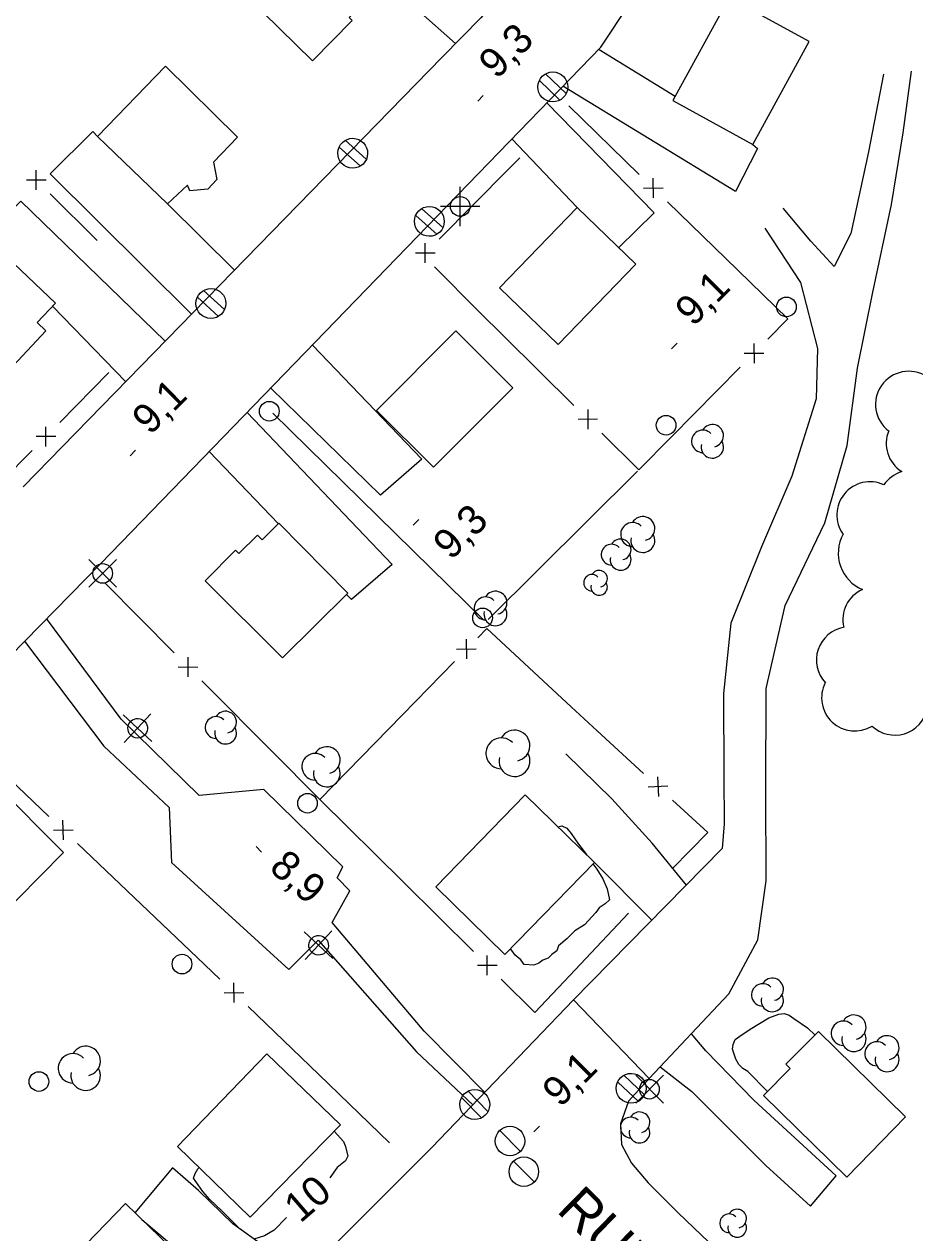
# Model space of a CAD drawing. Extents: x 381879 to 384696, y 5564785 to 5567594.
# Drawn here: x 383271.9 to 383362.5, y 5565478.7 to 5565601.7 of the extents above; entities that cross this region are included whole.
import ezdxf

# ---------------------------------------------------------------- set-up
doc = ezdxf.new("R2010")
doc.units = 0
for name, color, linetype in [('Niveau 1', 7, 'Continuous'), ('Niveau 19', 7, 'Continuous'), ('Niveau 21', 7, 'Continuous'), ('Niveau 22', 7, 'Continuous'), ('Niveau 3', 7, 'Continuous'), ('Niveau 31', 7, 'Continuous'), ('Niveau 36', 7, 'Continuous'), ('Niveau 37', 7, 'Continuous'), ('Niveau 41', 7, 'Continuous'), ('Niveau 44', 7, 'Continuous')]:
    doc.layers.add(name, color=color, linetype=linetype)

msp = doc.modelspace()

# ---------------------------------------------------------------- linework, layer by layer
at = {"layer": 'Niveau 1'}
for points in [[(383326.21, 5565520.01), (383326.61, 5565520.1), (383327.12, 5565519.86), (383327.57, 5565519.34), (383328.31, 5565518.24), (383329.12, 5565517.18), (383329.12, 5565517.17)], [(383329.78, 5565516.24), (383330.17, 5565515.69), (383330.78, 5565514.72), (383331.24, 5565513.69), (383331.47, 5565512.59), (383331.03, 5565512.17), (383330.41, 5565511.77), (383330.06, 5565511.31), (383328.91, 5565510.04), (383327.94, 5565509.43), (383327.13, 5565508.62)], [(383327.13, 5565508.62), (383326.29, 5565507.89), (383326.12, 5565507.4), (383325.58, 5565507.03), (383325.21, 5565506.64), (383324.68, 5565506.45), (383324.28, 5565506.14), (383323.76, 5565505.95), (383322.79, 5565506.02), (383322.45, 5565506.49), (383321.86, 5565506.96), (383321.52, 5565507.43), (383321.38, 5565507.6)], [(383347.56, 5565493.1), (383345.53, 5565495.12), (383345.02, 5565495.44), (383344.64, 5565495.83), (383344.34, 5565496.36), (383344, 5565497.38), (383344.05, 5565497.88), (383344.25, 5565498.36), (383344.72, 5565498.72), (383345.79, 5565499.42), (383347.68, 5565500.57), (383348.7, 5565500.96), (383349.23, 5565501.01), (383349.74, 5565500.86), (383350.21, 5565500.52), (383351.63, 5565499.57), (383352.39, 5565498.83)], [(383303.45, 5565489.04), (383304.41, 5565487.98), (383304.61, 5565487.48), (383304.85, 5565486.5), (383304.6, 5565486.04), (383303.76, 5565485.36)], [(383293.91, 5565479.04), (383292.02, 5565480.95), (383290.8, 5565482.09), (383290.07, 5565482.91), (383289.14, 5565484.25), (383289.28, 5565484.74), (383289.58, 5565485.22), (383289.7, 5565485.36)], [(383303.76, 5565485.36), (383303, 5565484.3)], [(383298.58, 5565480.26), (383297.33, 5565478.98), (383296.35, 5565478.4), (383295.27, 5565478.06)]]:
    msp.add_lwpolyline(points, dxfattribs=at)
at = {"layer": 'Niveau 19'}
for points in [[(383308.64, 5565606.08), (383311.95, 5565603.09), (383315.79, 5565599.7)], [(383330.36, 5565599.11), (383330.41, 5565599.08), (383338.14, 5565594.34)], [(383343.62, 5565503.02), (383346.56, 5565508.52), (383347.41, 5565514.53), (383347.36, 5565523.69), (383347.41, 5565534.07), (383349.35, 5565542.53), (383353.38, 5565550.95), (383355.65, 5565558.8), (383356.72, 5565566.68), (383358.24, 5565574.24), (383360.17, 5565583.33), (383361.36, 5565590.63), (383362.21, 5565596.9)], [(383359.35, 5565596.58), (383357.84, 5565588.69), (383356.03, 5565580.39), (383354.32, 5565577.02), (383351.97, 5565579.6), (383349.15, 5565582.97)], [(383346.04, 5565589.44), (383346.54, 5565589.02), (383344.29, 5565584.65), (383326.72, 5565595.35)], [(383332.4, 5565578.95), (383336.02, 5565582.47), (383325.08, 5565593.66)], [(383279.36, 5565590.24), (383278.87, 5565590.74), (383274.54, 5565586.43), (383288.94, 5565572.18)], [(383321.54, 5565590), (383321.54, 5565590), (383328.17, 5565583.03)], [(383286.24, 5565569.41), (383271.55, 5565583.65), (383267.95, 5565580.02)], [(383293.3, 5565576.64), (383286.47, 5565583.38)], [(383347.27, 5565580.93), (383350.89, 5565575.39), (383352.64, 5565568.69), (383352.51, 5565563.55), (383350.03, 5565555.69), (383346.92, 5565548.51), (383343.81, 5565540.74), (383343.08, 5565533.56), (383343.1, 5565525.2), (383343.15, 5565520.33), (383342.94, 5565517.79)], [(383274.79, 5565572.99), (383282.23, 5565565.29)], [(383301.23, 5565569.03), (383312.37, 5565557.43), (383308.15, 5565553.75), (383297.04, 5565564.62), (383297, 5565564.66)], [(383294.59, 5565562.18), (383309.35, 5565546.69), (383305.21, 5565543.13), (383304.71, 5565543.65)], [(383297.78, 5565550.85), (383290.73, 5565558.19)], [(383339.29, 5565514.08), (383335.81, 5565518.35), (383331.72, 5565522.87), (383327.02, 5565527.45)], [(383327.73, 5565502.33), (383342.94, 5565517.79)], [(383335.77, 5565510.5), (383329.93, 5565516.39)], [(383335.5, 5565494.4), (383343.62, 5565503.02)], [(383336.62, 5565495.59), (383336.63, 5565495.59), (383339.84, 5565493.07), (383347.37, 5565485.57), (383351.93, 5565481.42), (383354.53, 5565484.5), (383346.14, 5565492.19), (383341.26, 5565497.22), (383339.8, 5565498.96), (383339.8, 5565498.96)], [(383300.39, 5565474.39), (383293.12, 5565479.61), (383289.65, 5565483.01), (383287, 5565485.32), (383283.17, 5565480.75)], [(383283.88, 5565480.06), (383291.48, 5565473.65), (383296.45, 5565470.34)]]:
    msp.add_lwpolyline(points, dxfattribs=at)
at = {"layer": 'Niveau 21'}
for points in [[(383279.7, 5565546.8), (383330.59, 5565599.35), (383333.54, 5565603.77), (383335.2, 5565607.85), (383336.77, 5565613.62), (383337.23, 5565619.22), (383336.69, 5565623.71), (383333.54, 5565649.66), (383333.88, 5565651.87), (383335.17, 5565653.84), (383337.46, 5565655.87), (383338.63, 5565656.35), (383339.61, 5565656.47)], [(383225.4, 5565600.6), (383260.79, 5565637.22), (383264.27, 5565640.61), (383268.01, 5565643.77), (383272.04, 5565645.91), (383277.7, 5565648.06), (383282.77, 5565649.18), (383314.56, 5565653.12), (383317.26, 5565652.66), (383319.46, 5565651.5), (383321.49, 5565649.13), (383322.5, 5565646.69), (383322.83, 5565644.58), (383325.81, 5565617.8), (383325.38, 5565613.29), (383324.28, 5565610.19), (383321.91, 5565606.43), (383318.36, 5565602.32), (383314.44, 5565598.32), (383271.8, 5565554.6)], [(383279.7, 5565546.8), (383267.3, 5565534.2), (383254, 5565520.6)], [(383300.6, 5565474.6), (383313.4, 5565487.4), (383327.8, 5565502.4)], [(383327.8, 5565502.4), (383335.5, 5565494.4)], [(383335.5, 5565494.4), (383333.4, 5565492.1), (383332.6, 5565489.8), (383332.7, 5565487.7), (383333.7, 5565485.8), (383335.4, 5565483.8), (383338.5, 5565480.7), (383345.4, 5565474.1), (383355.1, 5565464.2), (383360.4, 5565459)]]:
    msp.add_lwpolyline(points, dxfattribs=at)
at = {"layer": 'Niveau 22'}
for points in [[(383318.77, 5565492.99), (383312.61, 5565499.23), (383303.23, 5565510.27), (383305.05, 5565513.51), (383303.75, 5565514.81), (383304.31, 5565515.95), (383296.28, 5565523.81), (383289.69, 5565523.2), (383281.76, 5565530.95), (383274.18, 5565541.19)], [(383271.92, 5565538.9), (383280.01, 5565528.23), (383286.64, 5565521.98), (383286.88, 5565516.39), (383298.82, 5565505.51), (383301.8, 5565508.47), (383311.82, 5565497.12), (383317.56, 5565491.73)]]:
    msp.add_lwpolyline(points, dxfattribs=at)
at = {"layer": 'Niveau 3'}
for p, q in [((383318.05, 5565593.84), (383318.62, 5565594.41)), ((383337.77, 5565568.64), (383338.34, 5565569.21)), ((383282.67, 5565557.75), (383283.24, 5565558.32)), ((383311.48, 5565550.71), (383312.05, 5565551.28)), ((383295.51, 5565518.02), (383296.06, 5565517.45)), ((383323.77, 5565488.98), (383324.34, 5565489.55))]:
    msp.add_line(p, q, dxfattribs=at)
at = {"layer": 'Niveau 31'}
for points in [[(383294.52, 5565604.57), (383302.33, 5565612.51), (383308.75, 5565606.19), (383304.98, 5565602.36), (383305.29, 5565602.06), (383301.24, 5565597.94)], [(383346.04, 5565589.44), (383351.78, 5565599.91), (383343.64, 5565604.37), (383337.9, 5565593.9)], [(383279.36, 5565590.24), (383286.28, 5565597.4), (383293.61, 5565590.19), (383291.15, 5565587.65), (383291.5, 5565585.86), (383290.6, 5565584.89), (383288.75, 5565584.7), (383288.5, 5565585.3), (383286.47, 5565583.38)], [(383320.27, 5565574.85), (383328.17, 5565583.03), (383334.14, 5565577.27), (383326.24, 5565569.09)], [(383267.95, 5565580.02), (383261.3, 5565572.94), (383269.33, 5565565.39), (383274.11, 5565570.47), (383273.21, 5565571.32), (383275.07, 5565573.29)], [(383307.76, 5565562.38), (383315.82, 5565570.46), (383321.62, 5565564.67), (383313.56, 5565556.59)], [(383298.17, 5565537.2), (383304.84, 5565543.78), (383297.82, 5565550.89), (383296.11, 5565549.21), (383295.64, 5565549.69), (383293.74, 5565547.83), (383293.41, 5565548.16), (383290.3, 5565545.04)], [(383266.5, 5565507.9), (383259.6, 5565514.7), (383269, 5565524.3), (383275.9, 5565517.4)], [(383322.88, 5565523.25), (383313.78, 5565513.89), (383320.83, 5565507.03), (383329.93, 5565516.39)], [(383361.6, 5565490.5), (383355.61, 5565484.38), (383347.14, 5565492.67), (383349.85, 5565495.43), (383349.42, 5565495.86), (383352.74, 5565499.18)], [(383304.1, 5565489.7), (383294.9, 5565480.3), (383287.5, 5565487.5), (383296.6, 5565496.9)], [(383282.2, 5565481.7), (383289.3, 5565474.8), (383280.3, 5565465.5), (383273.2, 5565472.4)]]:
    msp.add_lwpolyline(points, close=True, dxfattribs=at)
at = {"layer": 'Niveau 36'}
for p, q in [((383327.05, 5565594.61), (383324.96, 5565596.62)), ((383324.33, 5565595.95), (383326.42, 5565593.94)), ((383303.95, 5565589.16), (383306.11, 5565587.24)), ((383306.71, 5565587.94), (383304.55, 5565589.86)), ((383316.27, 5565581.13), (383316.28, 5565585.11)), ((383314.51, 5565580.99), (383312.34, 5565582.91)), ((383318.27, 5565583.11), (383314.28, 5565583.13)), ((383311.75, 5565582.21), (383313.92, 5565580.29)), ((383292.28, 5565572.63), (383290.13, 5565574.58)), ((383289.52, 5565573.89), (383291.67, 5565571.94)), ((383281.3, 5565547.2), (383278.48, 5565544.38)), ((383281.3, 5565544.38), (383278.48, 5565547.2)), ((383281.98, 5565531.4), (383284.89, 5565528.68)), ((383282.08, 5565528.59), (383284.8, 5565531.5)), ((383300.39, 5565509.32), (383303.3, 5565506.6)), ((383300.49, 5565506.51), (383303.21, 5565509.42)), ((383335.03, 5565492.75), (383332.92, 5565494.74)), ((383336.95, 5565494.73), (383334.13, 5565491.91)), ((383336.95, 5565491.91), (383334.13, 5565494.73)), ((383319.09, 5565491.06), (383317.06, 5565493.14)), ((383332.31, 5565494.05), (383334.42, 5565492.06)), ((383316.41, 5565492.48), (383318.44, 5565490.4)), ((383322.41, 5565486.98), (383320.29, 5565489.1)), ((383323.82, 5565483.87), (383321.7, 5565485.99))]:
    msp.add_line(p, q, dxfattribs=at)
for centre, radius in [((383316.27, 5565583.13), 1), ((383349.47, 5565572.91), 1), ((383296.84, 5565562.29), 1), ((383337.23, 5565560.87), 1), ((383279.88, 5565545.79), 1), ((383318.55, 5565541.27), 1), ((383300.73, 5565522.41), 1), ((383287.96, 5565506.04), 1), ((383273.39, 5565494.1), 1), ((383335.53, 5565493.32), 1), ((383321.34, 5565488.04), 1.5), ((383322.75, 5565484.93), 1.5)]:
    msp.add_circle(centre, radius, dxfattribs=at)
for centre, major_axis, ratio in [((383325.69, 5565595.29), (-0.01, -1.52), 0.999981), ((383305.33, 5565588.54), (0.03, 1.52), 0.999985), ((383313.13, 5565581.61), (-0.01, -1.52), 0.999982), ((383290.9, 5565573.25), (0.01, 1.52), 0.999981), ((383283.45, 5565530.04), (-0.048, -0.999), 0.999982), ((383301.86, 5565507.96), (-0.048, -0.999), 0.999982), ((383333.67, 5565493.41), (-0.02, -1.52), 0.999984), ((383317.75, 5565491.76), (0.02, 1.52), 0.99998)]:
    msp.add_ellipse(centre, major_axis=major_axis, ratio=ratio, dxfattribs=at)
at = {"layer": 'Niveau 37'}
for p, q in [((383273.13, 5565584.83), (383273.13, 5565586.83)), ((383272.13, 5565585.83), (383274.14, 5565585.83)), ((383335.94, 5565584), (383335.91, 5565586)), ((383334.92, 5565584.98), (383336.93, 5565585.01)), ((383312.72, 5565577.39), (383312.71, 5565579.39)), ((383313.72, 5565578.39), (383311.72, 5565578.39)), ((383345.17, 5565568.19), (383347.18, 5565568.2)), ((383346.17, 5565569.2), (383346.18, 5565567.2)), ((383329.25, 5565562.47), (383329.26, 5565560.46)), ((383330.26, 5565561.47), (383328.26, 5565561.46)), ((383275.11, 5565559.72), (383273.11, 5565559.71)), ((383274.11, 5565558.72), (383274.1, 5565560.72)), ((383316.88, 5565539.1), (383316.91, 5565537.1)), ((383315.89, 5565538.09), (383317.9, 5565538.11)), ((383287.58, 5565536.28), (383289.58, 5565536.27)), ((383288.57, 5565535.28), (383288.58, 5565537.28)), ((383336.36, 5565525.1), (383336.45, 5565523.1)), ((383337.41, 5565524.14), (383335.4, 5565524.05)), ((383275.89, 5565518.69), (383275.84, 5565520.69)), ((383274.87, 5565519.67), (383276.87, 5565519.72)), ((383319.03, 5565504.92), (383319.02, 5565506.93)), ((383318.03, 5565505.92), (383320.03, 5565505.93)), ((383292.24, 5565503.11), (383294.24, 5565503.15)), ((383293.26, 5565502.13), (383293.22, 5565504.13))]:
    msp.add_line(p, q, dxfattribs=at)
for points in [[(383327.32, 5565593.36), (383334.49, 5565586.39)], [(383321.17, 5565586.91), (383322.33, 5565588.08)], [(383314.13, 5565579.81), (383321.17, 5565586.91)], [(383274.55, 5565584.42), (383279.31, 5565579.67)], [(383337.36, 5565583.6), (383344.53, 5565576.63)], [(383320.73, 5565569.9), (383318.17, 5565572.43), (383313.65, 5565576.97)], [(383344.53, 5565576.63), (383349.62, 5565571.69), (383347.58, 5565569.62)], [(383327.84, 5565562.87), (383320.73, 5565569.9)], [(383275.51, 5565561.14), (383280.52, 5565566.22)], [(383344.77, 5565566.77), (383337.75, 5565559.65)], [(383337.75, 5565559.65), (383334.46, 5565556.32), (383330.68, 5565560.06)], [(383265.53, 5565559.13), (383269.68, 5565555.23), (383272.7, 5565558.29)], [(383280.12, 5565544.79), (383287.17, 5565537.7)], [(383318.98, 5565540.19), (383318.06, 5565539.24)], [(383327.58, 5565532.23), (383318.98, 5565540.19)], [(383315.7, 5565536.83), (383310.4, 5565531.4)], [(383289.99, 5565534.86), (383290.56, 5565534.28), (383297.04, 5565527.77)], [(383310.4, 5565531.4), (383302, 5565522.79)], [(383334.93, 5565525.45), (383330.21, 5565529.79), (383327.58, 5565532.23)], [(383267.17, 5565527.96), (383274.42, 5565521.07)], [(383297.04, 5565527.77), (383302, 5565522.79)], [(383302, 5565522.79), (383310.5, 5565514.37)], [(383337.88, 5565515.77), (383341.46, 5565519.45), (383337.88, 5565522.74)], [(383277.32, 5565518.31), (383284.56, 5565511.42)], [(383310.5, 5565514.37), (383317.61, 5565507.33)], [(383284.56, 5565511.42), (383289.5, 5565506.73), (383291.8, 5565504.52)], [(383327.42, 5565504.89), (383333.39, 5565511.23)], [(383320.45, 5565504.52), (383323.88, 5565501.12), (383327.42, 5565504.89)], [(383294.68, 5565501.74), (383301.88, 5565494.8)], [(383301.88, 5565494.8), (383309.08, 5565487.87)]]:
    msp.add_lwpolyline(points, dxfattribs=at)
at = {"layer": 'Niveau 41'}
for points in [[(383297.19, 5565562.09), (383318.62, 5565541.11)], [(383334.33, 5565556.19), (383319.13, 5565541.12)]]:
    msp.add_lwpolyline(points, dxfattribs=at)
at = {"layer": 'Niveau 44'}
for centre, radius, start, end in [((383341.93, 5565559.8), 1.14, 282.2692, 149.7262), ((383340.96, 5565559.23), 1.14, 44.1153, 269.8039), ((383341.93, 5565558.66), 1.14, 166.9368, 29.6212), ((383333.82, 5565549.75), 1.22, 44.1153, 269.8039), ((383334.86, 5565550.36), 1.22, 282.2692, 149.7262), ((383334.86, 5565549.14), 1.22, 166.9368, 29.6212), ((383358.76, 5565547.85), 4.01, 151.376, 247.2645), ((383331.69, 5565547.7), 1.06, 44.1153, 269.8039), ((383332.6, 5565548.23), 1.06, 282.2692, 149.7262), ((383332.6, 5565547.18), 1.06, 166.9368, 29.6212), ((383330.41, 5565545.26), 0.842, 282.2692, 149.7262), ((383329.68, 5565544.84), 0.842, 44.1153, 269.8039), ((383330.41, 5565544.41), 0.842, 166.9368, 29.6212), ((383319.86, 5565542.81), 1.17, 282.2692, 149.7262), ((383318.86, 5565542.23), 1.17, 44.1153, 269.8039), ((383319.86, 5565541.64), 1.17, 166.9368, 29.6212), ((383292.39, 5565530.66), 1.11, 282.2692, 149.7262), ((383291.43, 5565530.11), 1.11, 44.1153, 269.8039), ((383292.39, 5565529.55), 1.11, 166.9368, 29.6212), ((383320.46, 5565527.49), 1.57, 44.1153, 269.8039), ((383321.8, 5565528.27), 1.57, 282.2692, 149.7262), ((383302.7, 5565526.8), 1.36, 282.2692, 149.7262), ((383301.52, 5565526.12), 1.36, 44.1153, 269.8039), ((383321.8, 5565526.7), 1.57, 166.9368, 29.6212), ((383302.7, 5565525.44), 1.36, 166.9368, 29.6212), ((383348.03, 5565503.48), 1.14, 282.2692, 149.7262), ((383347.06, 5565502.91), 1.14, 44.1153, 269.8039), ((383348.03, 5565502.34), 1.14, 166.9368, 29.6212), ((383356.34, 5565499.63), 1.24, 282.2692, 149.7262), ((383355.27, 5565499.01), 1.24, 44.1153, 269.8039), ((383356.34, 5565498.39), 1.24, 166.9368, 29.6212), ((383358.68, 5565496.93), 1.22, 44.1153, 269.8039), ((383359.72, 5565497.54), 1.22, 282.2692, 149.7262), ((383276.86, 5565495.44), 1.5, 44.1153, 269.8039), ((383278.15, 5565496.19), 1.5, 282.2692, 149.7262), ((383359.72, 5565496.32), 1.22, 166.9368, 29.6212), ((383278.15, 5565494.69), 1.5, 166.9368, 29.6212), ((383334.52, 5565489.95), 1.05, 282.2692, 149.7262), ((383333.62, 5565489.42), 1.05, 44.1153, 269.8039), ((383334.52, 5565488.9), 1.05, 166.9368, 29.6212), ((383344.46, 5565480.15), 0.949, 282.2692, 149.7262), ((383343.64, 5565479.68), 0.949, 44.1153, 269.8039), ((383344.46, 5565479.21), 0.949, 166.9368, 29.6212)]:
    msp.add_arc(centre, radius, start, end, dxfattribs=at)
for centre, major_axis, ratio, start_param, end_param in [((383361.91, 5565562.98), (-2.42, -2.35), 0.999937, 3.369272, 6.431887), ((383363.02, 5565559.02), (1.17, -3.18), 0.999936, 3.968742, 5.365621), ((383362.21, 5565552.94), (0.82, 3.27), 0.999891, 0.546454, 1.234448), ((383357.98, 5565551.74), (-1.49, -3.03), 0.999937, 3.167758, 5.792852), ((383358.59, 5565541.08), (-1.33, -3.1), 0.999937, 3.968994, 5.347737), ((383355.91, 5565536.99), (-3.38, -0.09), 0.99885, 4.865596, 7.013045), ((383356.43, 5565533.14), (2.44, -2.33), 0.999984, 3.430589, 6.020737), ((383360.49, 5565532.72), (1.28, -3.13), 0.998622, 5.14302, 7.243547)]:
    msp.add_ellipse(centre, major_axis=major_axis, ratio=ratio, start_param=start_param, end_param=end_param, dxfattribs=at)

# ---------------------------------------------------------------- texts
at = {"layer": 'Niveau 1'}
msp.add_text('10', height=3, rotation=40.7956, dxfattribs=at).set_placement((383300, 5565479.62))
at = {"layer": 'Niveau 21'}
msp.add_text('RUE PAPINEAU', height=4, rotation=315.5295, dxfattribs=at).set_placement((383325.97, 5565480.91))
at = {"layer": 'Niveau 3'}
for s, rotation, p in [('9,3  ', 44.7717, (383319.98, 5565595.98)), ('9,1', 44.7717, (383339.98, 5565570.81)), ('9,1  ', 44.7717, (383284.71, 5565559.78)), ('9,3', 44.7717, (383315.34, 5565547.05)), ('8,9  ', 318.2783, (383296.71, 5565515.68)), ('9,1  ', 44.7717, (383326.46, 5565491.37))]:
    msp.add_text(s, height=3, rotation=rotation, dxfattribs=at).set_placement(p)

doc.saveas('drawing.dxf')
